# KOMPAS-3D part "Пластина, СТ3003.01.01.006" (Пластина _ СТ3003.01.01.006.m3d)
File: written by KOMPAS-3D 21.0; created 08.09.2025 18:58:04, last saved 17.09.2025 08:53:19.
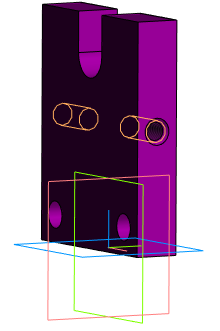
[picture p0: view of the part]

Document properties: Полное имя файла: C:\Users\1\Yandex.Disk\Документы\Новая папка\Стапель №2\Стапель _ СТ3003.00.00.000\Опора _ СТ3003.01.00.000\3D\Кронштейн _ СТ3003.01.01.000\Пластина _ СТ3003.01.01.006.m3d

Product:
- Part/product: Пластина  | designation СТ3003.01.01.006
    Материал: Лист$dБ-ПН-НО-16 ГОСТ 19903-2015;Ст3сп ГОСТ 14637-89$ (density 7850 kg/m3)
    Масса: 0.669577
    Форматы листов документа: A4

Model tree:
1. Эскиз:1
2. Элемент выдавливания:1
     Расстояние 1 = 16
3. Эскиз:3  (with: Элемент выдавливания:1)
4. ЛСК:2  (with: Плоскость XY, Плоскость ZX, Плоскость ZY, Ось X, Ось Y, Ось Z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)
     Ось X. X = 1; Ось Y. Y = 1; Ось Z. Z = 1; Координата X = 35; Координата Z = 45; Точка начала. Х = 35; Точка начала. Z = 45
5. Эскиз:4
6. Элемент вращения:1
     Угол 1 = 360
7. Смещенная плоскость:1  (with: Элемент выдавливания:1)
     Расстояние = 0.923418
8. Условное изображение резьбы:1  (with: Элемент вращения:1)  (labels: 8x1,25)
     Длина резьбы = 19.0766; Шаг резьбы = 1.25; Номинальный диаметр резьбы = 8
9. Подгонка:1
10. Отверстие М8x20/1,6x45°
11. Эскиз:7  (with: Элемент выдавливания:1)
12. ЛСК:5  (with: Плоскость XY, Плоскость ZX, Плоскость ZY, Ось X, Ось Y, Ось Z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)
     Ось X. X = -1; Ось Y. Y = 1; Ось Z. Z = -1; Координата X = -35; Координата Z = 45; Точка начала. Х = -35; Точка начала. Z = 45
13. Эскиз:8
14. Элемент вращения:2
     Угол 1 = 360
15. Смещенная плоскость:2  (with: Элемент выдавливания:1)
     Расстояние = 0.923418
16. Условное изображение резьбы:2  (with: Элемент вращения:2)  (labels: 8x1,25)
     Длина резьбы = 19.0766; Шаг резьбы = 1.25; Номинальный диаметр резьбы = 8
17. Подгонка:2
18. Отверстие М8x20/1,6x45° (1)  (labels: Лист$dБ-ПН-НО-16 ГОСТ 19903-2015;Ст3сп ГОСТ 14637-89$)

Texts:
  KTE.LIST=LTWD36N5dmSErgwNQxupvb
  Edge1
  Edge2
  СТ3003.01.01.006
